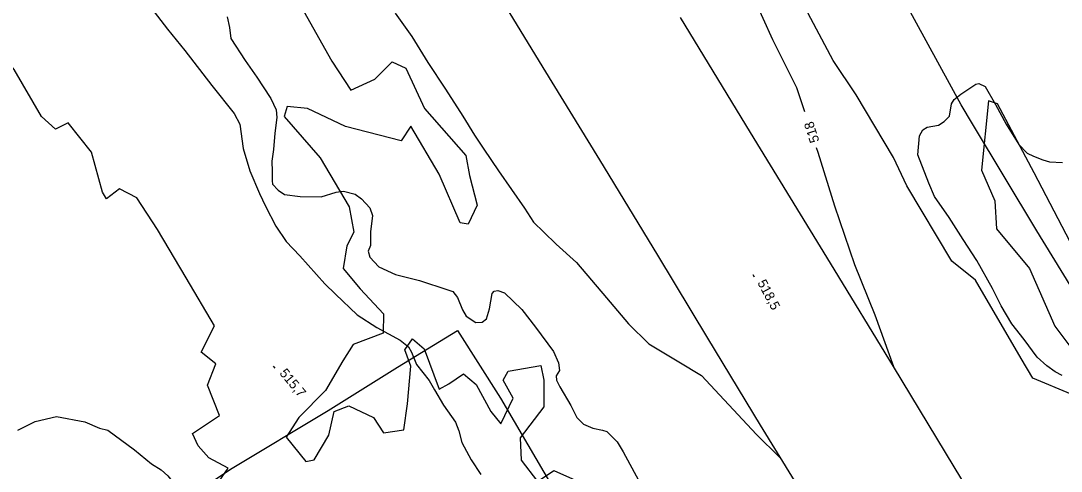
# Model space of a CAD drawing. Extents: x 347312 to 350503, y 6073086 to 6076432.
# Drawn here: x 349515.6 to 349840.3, y 6074636.9 to 6074777.4 of the extents above; entities that cross this region are included whole.
import ezdxf

# ---------------------------------------------------------------- set-up
doc = ezdxf.new("R2010")
doc.units = 0
for name, color, linetype in [('Level 2', 7, 'Continuous'), ('Level 25', 7, 'Continuous'), ('Level 3', 7, 'Continuous'), ('Level 37', 7, 'Continuous'), ('Level 4', 7, 'Continuous'), ('Level 44', 7, 'Continuous')]:
    doc.layers.add(name, color=color, linetype=linetype)

msp = doc.modelspace()

# ---------------------------------------------------------------- linework, layer by layer
at = {"layer": 'Level 2'}
for points in [[(349760.29, 6074749.01), (349757.82, 6074756.49), (349750.33, 6074771.48), (349744.3, 6074784.87), (349740.55, 6074799.03), (349734.21, 6074816.38), (349728.85, 6074826.32), (349719.71, 6074838.45), (349712.77, 6074850.29), (349712.69, 6074852.97), (349713.75, 6074854.46), (349715.61, 6074855.28)], [(349579.98, 6074778.63), (349580.71, 6074775.32), (349581.14, 6074771.88), (349585.62, 6074765.06), (349589.26, 6074759.81), (349591.24, 6074756.78), (349593.61, 6074753.15), (349595.27, 6074749.7), (349595.47, 6074747.3), (349594.93, 6074742.33), (349594.46, 6074737.28), (349594, 6074733.61), (349594.08, 6074730.42), (349594.04, 6074727.52), (349594.18, 6074726.42), (349595.94, 6074724.57), (349597.89, 6074723.28), (349602.84, 6074722.6), (349609.35, 6074722.47), (349614.01, 6074723.98), (349616.35, 6074724.26), (349619.98, 6074723.37), (349621.99, 6074721.87)], [(349632.5, 6074779.82), (349637.66, 6074772.54), (349642.62, 6074764.4), (349648.14, 6074756.07), (349653.59, 6074747.69), (349657.25, 6074741.8), (349660.14, 6074737.42), (349664.75, 6074730.61), (349672.8, 6074718.95), (349675.62, 6074714.64), (349678.81, 6074711.47), (349682.75, 6074707.74), (349689.09, 6074702.05), (349698.39, 6074690.97), (349705.26, 6074682.88), (349711.67, 6074676.63), (349721.02, 6074670.99), (349728.03, 6074666.74), (349733.7, 6074660.77), (349745.27, 6074648.36), (349752.45, 6074641.29), (349752.58, 6074641.22)], [(349805.46, 6074747.66), (349806.06, 6074751.57), (349806.91, 6074752.87), (349808.97, 6074754.52), (349813.72, 6074757.67), (349814.62, 6074757.83), (349816.61, 6074756.98), (349819.82, 6074751.28), (349823.14, 6074745.18), (349827.14, 6074738.82), (349829.73, 6074736.17), (349831.66, 6074735.2), (349834.59, 6074734.02), (349836.69, 6074733.48), (349840.76, 6074733.25)], [(349840.64, 6074666.79), (349838.48, 6074667.87), (349835.86, 6074669.78), (349832.8, 6074672.5), (349828.77, 6074678.04), (349824.91, 6074682.92), (349821.61, 6074688.55), (349818.86, 6074693.87), (349814.03, 6074702.64), (349809.78, 6074709.21), (349805.4, 6074716.07), (349800.81, 6074722.6), (349799.01, 6074726.79), (349795.64, 6074735.6), (349796.1, 6074741.55), (349797.21, 6074743.43), (349798.5, 6074744.21), (349802.04, 6074744.88), (349803.77, 6074746.02), (349805.46, 6074747.66)], [(349788.08, 6074669.45), (349782.29, 6074685.62), (349775.94, 6074701.29), (349769.66, 6074719.58), (349764.46, 6074736.39), (349763.99, 6074737.82)], [(349621.99, 6074721.87), (349624.56, 6074719.09), (349625.34, 6074716.65), (349624.72, 6074711.61), (349624.8, 6074707.33), (349624.03, 6074705.57), (349624.56, 6074703.72), (349627.34, 6074700.72), (349632.6, 6074698.27), (349640.08, 6074696.42), (349648.87, 6074693.53), (349650.42, 6074693), (349651.96, 6074691.08), (349653.44, 6074687.22), (349654.62, 6074685.26), (349657.67, 6074683.33), (349659.63, 6074683.42), (349660.93, 6074684.42), (349661.93, 6074687.62), (349662.68, 6074692.35), (349663.38, 6074693.1), (349664.47, 6074693.25), (349666.53, 6074692.61), (349672.04, 6074687.4), (349676.24, 6074681.84), (349681.89, 6074674.31), (349683.39, 6074670.74), (349683.74, 6074668.32), (349682.69, 6074666.72), (349682.82, 6074665.34), (349683.84, 6074663.25), (349687.29, 6074657.45), (349689.21, 6074653.71), (349691.24, 6074651.55), (349694.19, 6074650.35), (349697.19, 6074649.72), (349698.53, 6074649.27), (349701.72, 6074646.1), (349703.61, 6074643.01), (349708.45, 6074634.09)], [(349514.65, 6074649.76), (349514.87, 6074649.84), (349520.04, 6074652.45), (349526.69, 6074654), (349535.62, 6074652.35), (349540.16, 6074650.31), (349542.79, 6074649.67), (349551.06, 6074643.58), (349556.36, 6074639.26), (349559.41, 6074637.32), (349561.53, 6074635.51), (349564.26, 6074631.93), (349566.78, 6074628.76), (349569.16, 6074627.11), (349575.71, 6074623.48), (349581.62, 6074619.82), (349584.41, 6074617.25), (349586.84, 6074614.48), (349588.77, 6074611.96)]]:
    msp.add_lwpolyline(points, dxfattribs=at)
at = {"layer": 'Level 25'}
msp.add_lwpolyline([(349656.2, 6074799.57), (349678.59, 6074762.81), (349696.19, 6074734.05), (349714.33, 6074704.28), (349729.9, 6074678.44), (349746.4, 6074651.32), (349762.26, 6074625.41), (349775.55, 6074603.7), (349792.46, 6074575.9), (349809.32, 6074548.17), (349826.76, 6074519.48), (349842.65, 6074493.39), (349853.14, 6074499.67), (349880.91, 6074516.43), (349862.22, 6074547.58), (349840.44, 6074583.38), (349822.76, 6074612.14), (349806.96, 6074638.27), (349788, 6074669.6), (349768.37, 6074701.83), (349743.34, 6074742.62), (349721.53, 6074778.43)], dxfattribs=at)
at = {"layer": 'Level 3'}
for p, q in [((349744.09, 6074698.27), (349744.47, 6074697.57)), ((349594.37, 6074669.66), (349594.88, 6074669.04))]:
    msp.add_line(p, q, dxfattribs=at)
at = {"layer": 'Level 37'}
for points in [[(349937.19, 6074540.97), (349874.05, 6074644.62), (349832.75, 6074711.94), (349812.61, 6074745.27), (349809.11, 6074751.23), (349749.75, 6074859.9), (349724.27, 6074900.83), (349698.65, 6074944.47), (349688.46, 6074960.35), (349667.84, 6074994.28), (349654.77, 6075015.26), (349644.24, 6075033.23), (349636.23, 6075046.12), (349615.69, 6075079.37)], [(349516.45, 6074598.14), (349531.64, 6074607.15), (349571.6, 6074631.21), (349581.05, 6074637.58), (349611.57, 6074655.88), (349633.21, 6074669.35), (349651.95, 6074680.82), (349665.38, 6074659.69), (349694.13, 6074610.55), (349714.21, 6074577.67), (349725.42, 6074558.23), (349742.4, 6074531.65), (349763.01, 6074498.25), (349777.7, 6074474), (349792.93, 6074449.18), (349800.41, 6074436.45), (349803.89, 6074430.82)]]:
    msp.add_lwpolyline(points, dxfattribs=at)
at = {"layer": 'Level 4'}
msp.add_lwpolyline([(349554.08, 6074784.43), (349561.42, 6074774.82), (349566.75, 6074768.18), (349575.22, 6074757.21), (349582.16, 6074748.55), (349583.96, 6074745.18), (349585.05, 6074737.54), (349587.05, 6074730.59), (349590.06, 6074723.6), (349591.97, 6074719.57), (349595.17, 6074713.34), (349598.47, 6074708.54), (349602.65, 6074704.11), (349610.54, 6074695.38), (349613.86, 6074692.1), (349620.58, 6074685.69), (349626.72, 6074681.7), (349634.04, 6074677.82), (349636.65, 6074675.74), (349637.55, 6074674.03), (349639.1, 6074670.24), (349643.07, 6074665.26), (349644.75, 6074662.33), (349647.55, 6074657.5), (349651.32, 6074652.21), (349652.37, 6074649.5), (349653.28, 6074645.86), (349656.15, 6074640.49), (349659.18, 6074635.92)], dxfattribs=at)
at = {"layer": 'Level 44'}
for points in [[(349601.97, 6074783.87), (349612.72, 6074764.87), (349618.62, 6074755.74), (349626.09, 6074759.17), (349631.48, 6074764.59)], [(349551.84, 6074722.24), (349546.4, 6074725.02), (349542.37, 6074721.93), (349541.1, 6074724.01), (349537.69, 6074736.45), (349530.39, 6074745.62), (349526.38, 6074743.6), (349522.03, 6074747.6), (349513.52, 6074762.22), (349507.48, 6074770.06), (349509.34, 6074774.33), (349506.71, 6074776.78), (349497.13, 6074783.46)], [(349920.79, 6074527.41), (349913.51, 6074528.12), (349899.44, 6074549.79), (349888.41, 6074569.62), (349866.85, 6074597.73), (349852.97, 6074620.25), (349853.13, 6074625.38), (349851, 6074640.67), (349847.77, 6074647.7), (349849.04, 6074654.35), (349843.5, 6074660.93), (349831.52, 6074665.97), (349827.88, 6074672.07), (349813.64, 6074696.49), (349806.25, 6074702.43), (349792.21, 6074725.9), (349788.01, 6074734.81), (349776.34, 6074754.38), (349769.21, 6074765.02), (349760.48, 6074781.46)], [(349631.48, 6074764.59), (349635.76, 6074762.66), (349641.57, 6074750.02), (349654.49, 6074735.44), (349655.61, 6074729.21), (349658.06, 6074719.9), (349655.23, 6074713.94), (349652.76, 6074714.4), (349646.22, 6074729.55), (349637.3, 6074744.52), (349634.35, 6074739.94), (349616.9, 6074744.44), (349605.07, 6074750.08), (349598.78, 6074750.64), (349597.76, 6074747.54), (349609, 6074734.66), (349618.14, 6074719.43), (349619.6, 6074711.52), (349617.33, 6074707.22), (349616.26, 6074700.19), (349621.52, 6074693.83), (349628.84, 6074686.06), (349628.67, 6074679.93), (349619.32, 6074676.42), (349616.08, 6074671.3), (349610.68, 6074662.13), (349602.42, 6074653.69), (349598.43, 6074647.5), (349604.55, 6074639.93), (349607.2, 6074640.51), (349611.74, 6074648.21), (349613.4, 6074655.59), (349617.95, 6074657.31), (349625.74, 6074653.68), (349628.78, 6074648.91), (349635.2, 6074649.82), (349636.29, 6074657.91), (349637.31, 6074669.69), (349635.51, 6074674.76), (349637.86, 6074678.23), (349641.47, 6074675.13), (349646.22, 6074662.51), (349649.22, 6074664.13), (349653.75, 6074667.33), (349657.73, 6074663.95), (349662.3, 6074655.53), (349665.44, 6074651.74), (349669.28, 6074659.75), (349666.15, 6074665.34), (349667.71, 6074668.15)], [(349848.19, 6074698.93), (349831.95, 6074730.04), (349820.48, 6074751.54), (349817.64, 6074752.43), (349815.49, 6074730.8), (349819.63, 6074721.24), (349820.12, 6074712.48), (349830.48, 6074700.13), (349838.38, 6074682.2), (349850.18, 6074666.37)], [(349577.27, 6074633.53), (349580.28, 6074637.85), (349574.31, 6074641.07), (349571.01, 6074644.88), (349569.24, 6074648.64), (349577.57, 6074654.29), (349573.9, 6074663.79), (349576.47, 6074670.44), (349571.85, 6074674.04), (349576.1, 6074682.26), (349567.17, 6074697.21), (349558.24, 6074712.33), (349551.84, 6074722.24)], [(349667.71, 6074668.15), (349677.94, 6074669.86), (349678.82, 6074665.37), (349678.84, 6074657.02), (349671.44, 6074647.37), (349671.83, 6074640.38), (349676.89, 6074633.72), (349682, 6074637.12), (349691.51, 6074632.85)]]:
    msp.add_lwpolyline(points, dxfattribs=at)

# ---------------------------------------------------------------- texts
at = {"layer": 'Level 2'}
msp.add_text('518', height=3, rotation=108.0734, dxfattribs=at).set_placement((349764.91, 6074739.93))
at = {"layer": 'Level 3'}
for s, rotation, p in [('518,5', 298.1793, (349745.42, 6074695.72)), ('515,7', 309.5679, (349596.18, 6074667.42))]:
    msp.add_text(s, height=3, rotation=rotation, dxfattribs=at).set_placement(p)

doc.saveas('drawing.dxf')
